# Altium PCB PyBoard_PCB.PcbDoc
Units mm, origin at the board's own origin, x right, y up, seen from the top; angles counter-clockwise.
Board outline 70.69 x 58.01 mm, 2 copper layers (Top Layer, Bottom Layer); 72 components, 78 nets, 255 pads, 64 vias.
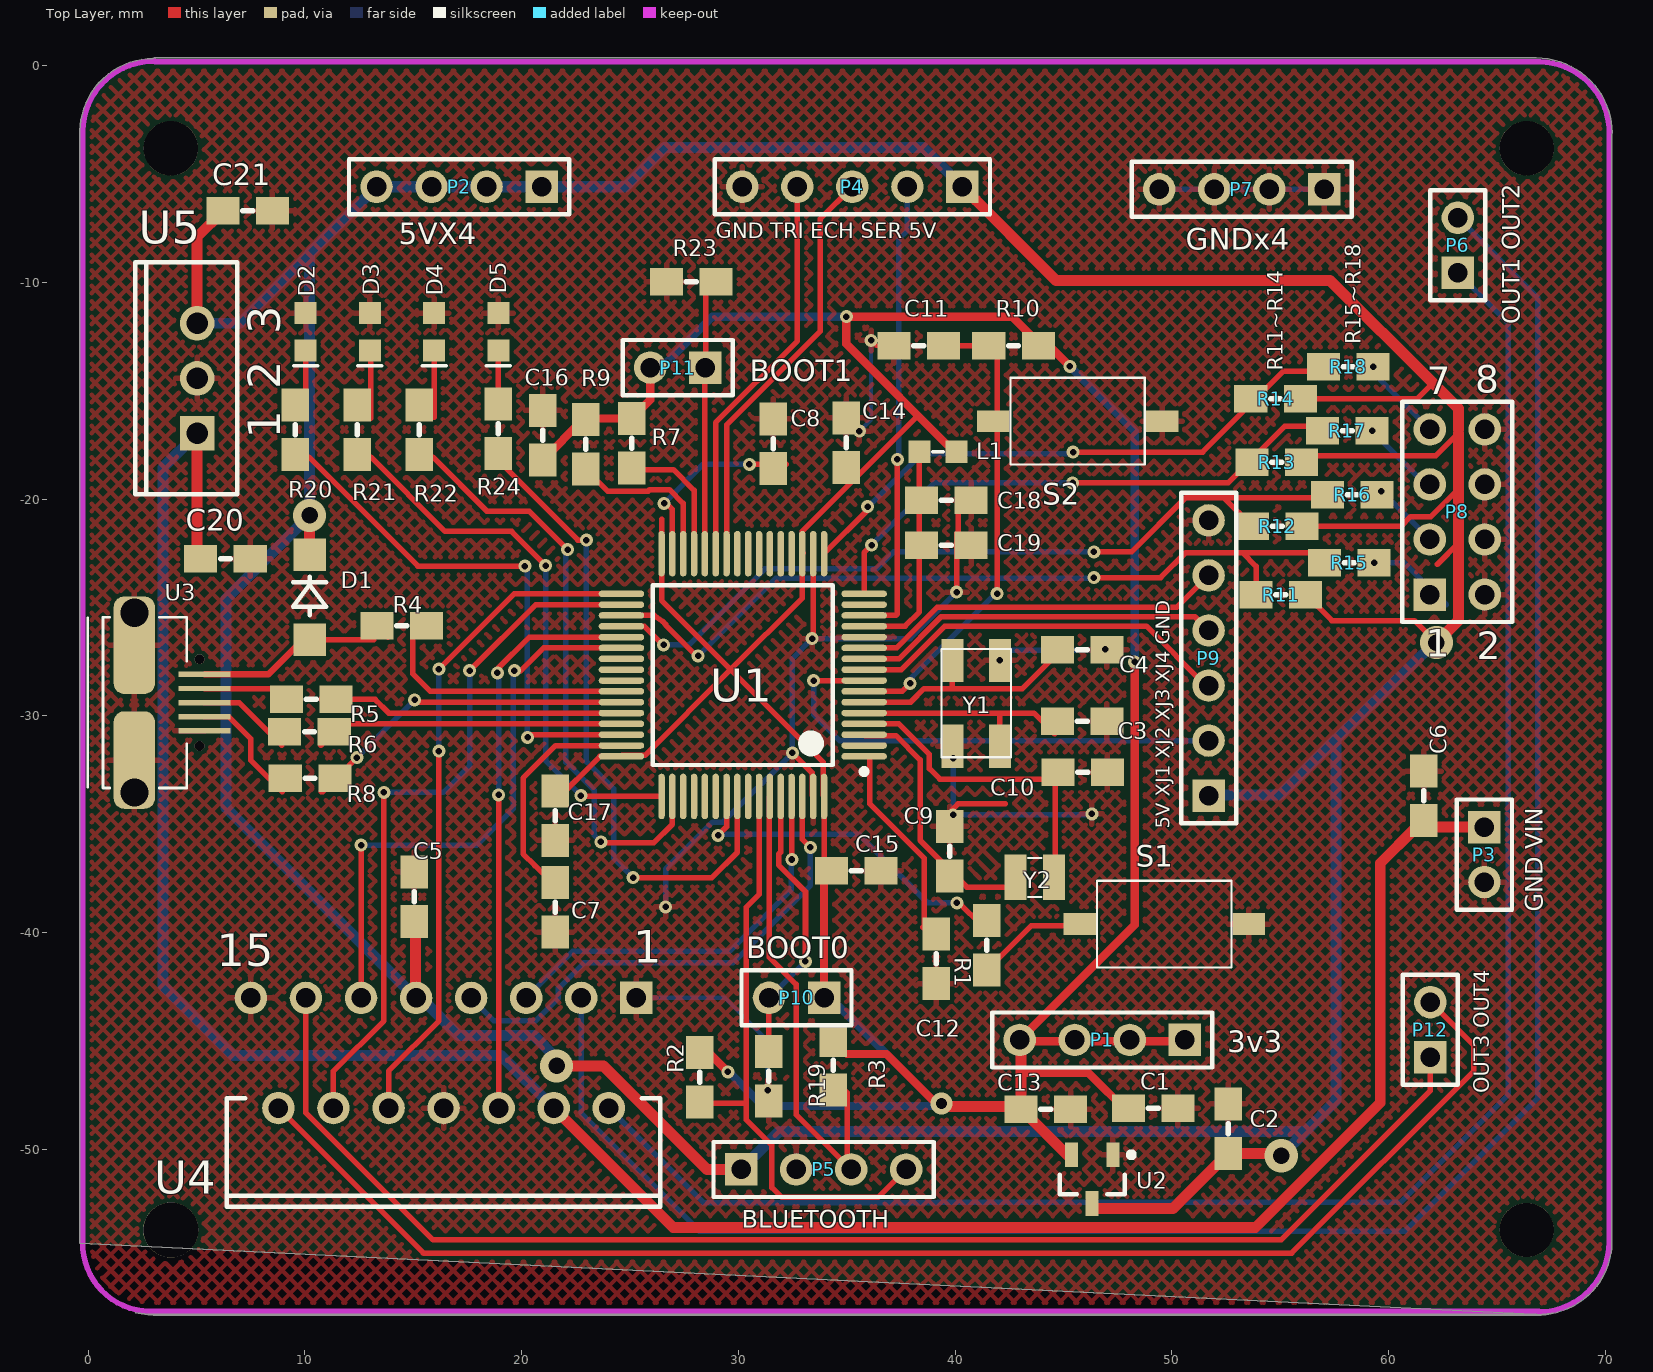
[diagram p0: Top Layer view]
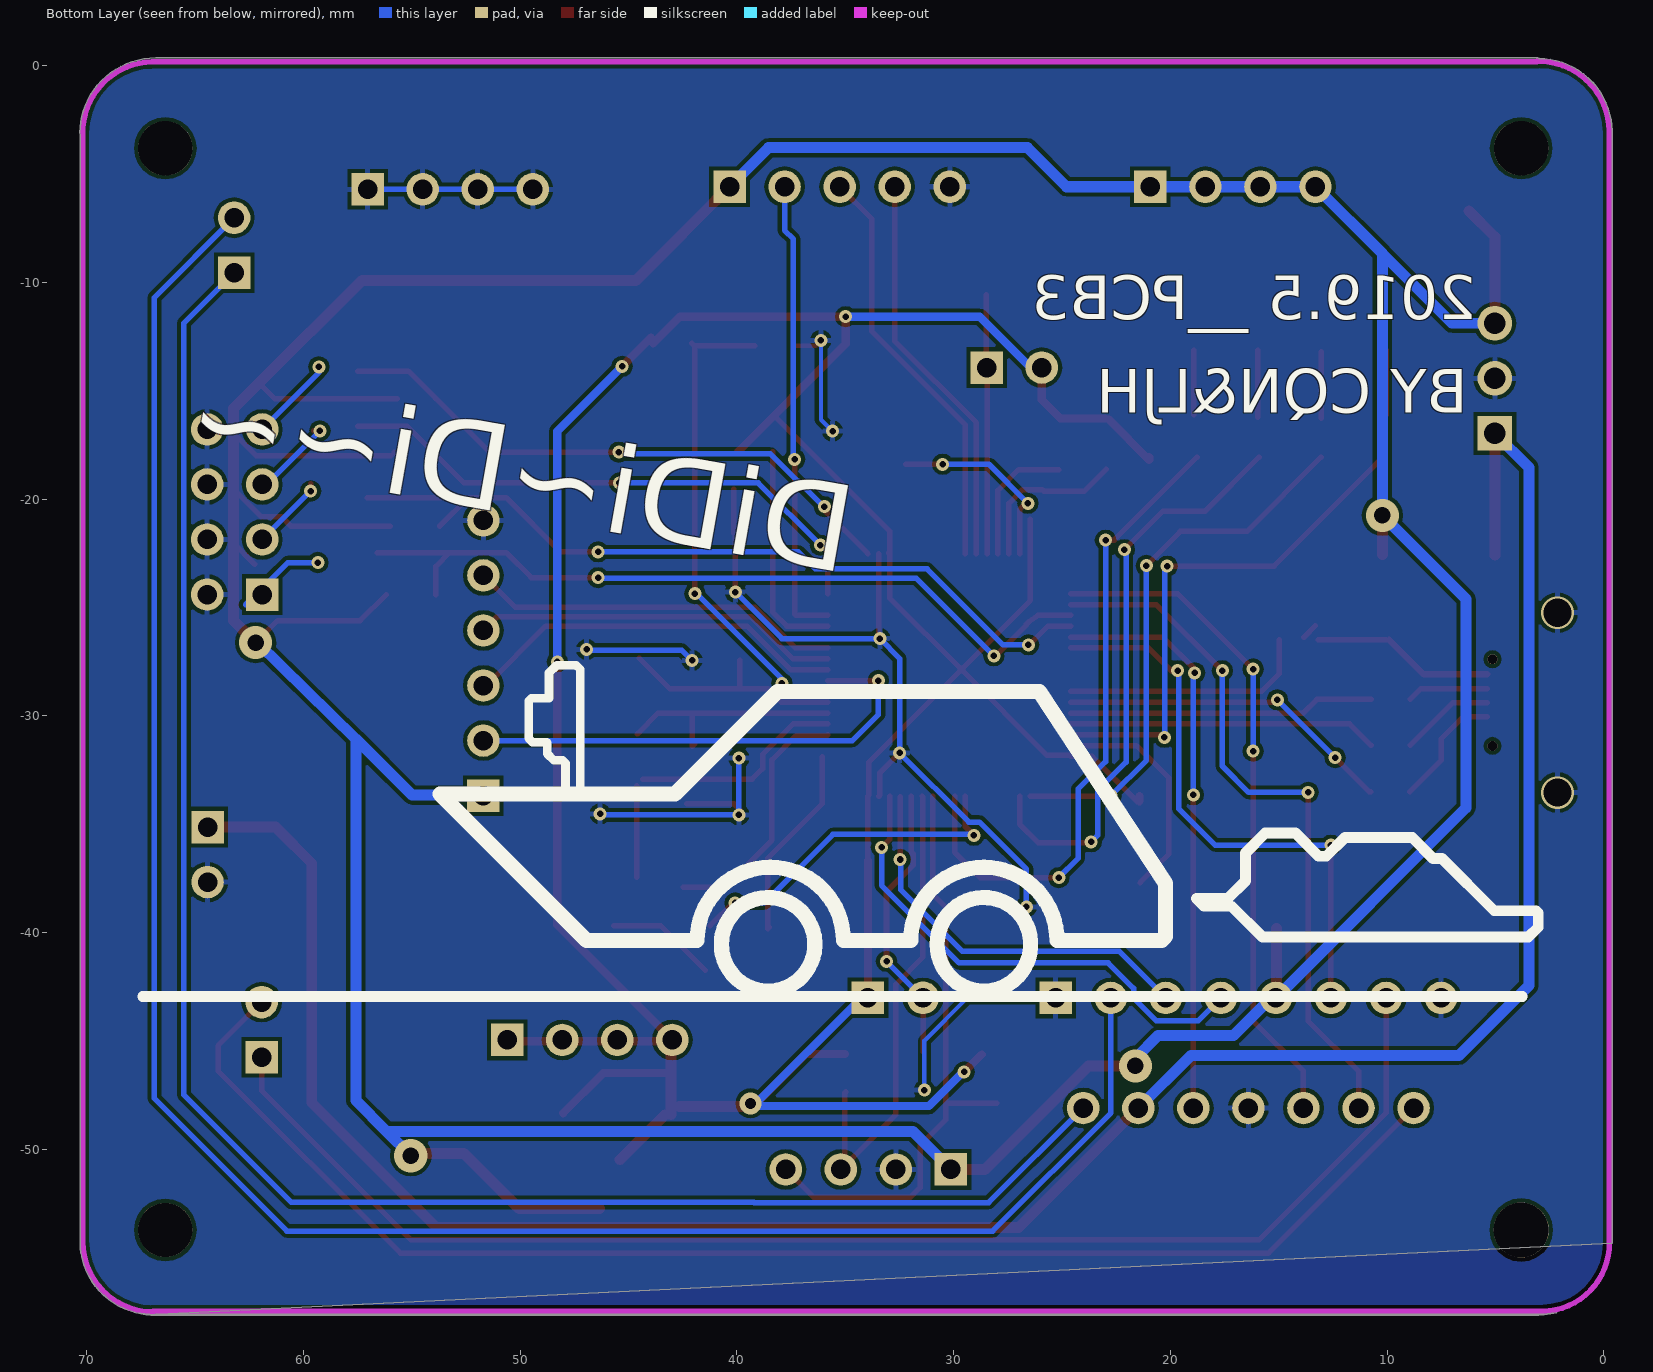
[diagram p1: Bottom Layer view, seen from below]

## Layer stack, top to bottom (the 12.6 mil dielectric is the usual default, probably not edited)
Top Layer: signal copper 0.0356
Dielectric: dielectric 0.32, FR-4, Dk 4.8
Bottom Layer: signal copper 0.0356

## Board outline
-0.381,-54.323 cw(c-0.254,-54.319) -0.381,-54.319 -0.381,-2.997 cw(c-0.254,-2.997) -0.381,-2.995 cw(c3.01,-3.061) -0.286,-2.259 cw(c3.01,-3.061) 2.208,0.235 cw(c3.01,-3.061) 2.972,0.331 cw(c3.048,0.229) 3.03,0.355 cw(c3.048,0.229) 3.048,0.356 66.802,0.356 cw(c66.802,-3.175) 68.892,-0.329 cw(c66.916,-3.086) 70.075,-1.849 cw(c66.916,-3.086) 70.308,-3.086 cw(c66.916,-3.086) 70.308,-3.099 cw(c66.916,-3.086) 70.308,-3.151 cw(c66.916,-3.086) 70.308,-3.152 70.308,-3.151 70.308,-54.305 cw(c70.18,-54.305) 70.308,-54.308 cw(c66.916,-54.242) 70.212,-55.044 cw(c66.916,-54.242) 67.718,-57.537 cw(c66.916,-54.242) 66.878,-57.633 cw(c66.916,-54.242) 66.85,-57.633 cw(c66.853,-57.506) 66.773,-57.605 2.819,-57.605 cw(c2.819,-57.478) 2.817,-57.605 cw(c2.88,-54.344) 2.179,-57.53 ccw(c3.124,-54.127) 3.03,-57.657 ccw(c3.124,-54.127) 3.124,-57.658 ccw(c3.124,-57.531) 3.228,-57.605 3.048,-57.658 cw(c3.048,-57.531) 3.03,-57.657 cw(c3.048,-57.531) 2.944,-57.605 3.048,-57.658 66.802,-57.658 ccw(c66.802,-54.127) 67.718,-57.537 66.878,-57.633 cw(c66.802,-57.531) 66.802,-57.658 cw(c66.802,-57.531)

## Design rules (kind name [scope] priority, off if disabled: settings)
Clearance [All] p1: gap=0.178
PolygonConnect [All] p1: connectstyle=Relief reliefconductorwidth=0.254 reliefentries=4 polygonreliefangle="90 Angle"
RoutingVias [All] p1: holewidth=0.3 width=0.6 viastyle="Through Hole" minholewidth=0.2 minwidth=0.5 maxholewidth=1.27 maxwidth=3.81
SilkscreenOverComponentPads [All] p1: minsilkscreentomaskgap=0.254
SolderMaskExpansion [All] p1: expansion=0.102
TestPointUsage [All] p1: valid=0 allowmultiple=FALSE
Testpoint [All] p1: side=15 testpointundercomponent=TRUE minsize=1.016 maxsize=2.54 preferedsize=1.524 minholesize=0 maxholesize=1.016 preferedholesize=0.813 testpointgrid=0.025 style=1023 order=0123456789
Width [All] p1: maxlimit=0.508 minlimit=0.178 preferedwidth=0.203
23 further rules are at their usual default settings.

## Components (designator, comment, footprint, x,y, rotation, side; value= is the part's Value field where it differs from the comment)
C1 "4u7" SMD0805 50.275,-48.1 r180 top
C2 "2u2" SMD0805 52.596,-47.905 r270 top
C3 "18p" SMD0805 47,-30.25 r180 top
C4 "18p" SMD0805 47,-26.95 r180 top
C5 "100n" SMD0805 15.05,-37.2 r270 top
C6 "100n" SMD0805 61.625,-32.55 r270 top
C7 "4u7" SMD0805 21.55,-39.975 r90 top
C8 "4u7" SMD0805 31.6,-16.3 r270 top
C9 "2.2p" SMD0805 39.75,-35.1 r270 top
C10 "2.2p" SMD0805 47.025,-32.6 r180 top
C11 "104" SMD0805 37.175,-12.915 r0 top
C12 "104" SMD0805 39.125,-42.35 r90 top
C13 "2u2" SMD0805 45.325,-48.15 r180 top
C14 "104" SMD0805 34.975,-16.25 r270 top
C15 "104" SMD0805 36.575,-37.15 r180 top
C16 "104" SMD0805 20.975,-15.9 r270 top
C17 "104" SMD0805 21.55,-35.75 r90 top
C18 "4u7" SMD0805 38.445,-20.05 r0 top
C19 "104" SMD0805 38.445,-22.125 r0 top
C20 "0.33u" SMD0805 7.475,-22.75 r180 top
C21 "0.1u" SMD0805 8.5,-6.7 r180 top
D1 "Diode" "SS24 - SMALL" 10.211,-26.492 r90 top
D2 "LED RED" LED0603 10.025,-12.275 r90 top
D3 "LED GREEN" LED0603 12.992,-12.275 r90 top
D4 "LED Yellow" LED0603 15.958,-12.275 r90 top
D5 "LED Blue" LED0603 18.925,-12.275 r90 top
L1 "1uH" SMD0603 39.209,-17.813 r180 top
P1 "3v3" HDR1X4 50.596,-44.955 r180 top
P2 "5VX4" HDR1X4 20.921,-5.585 r180 top
P3 "GND VIN" HDR1X2 64.421,-35.13 r270 top
P4 "Header 5_SUPERVOICE" HDR1X5 40.336,-5.585 r180 top
P5 "BLUETOOTH" HDR1X4 30.121,-50.93 r0 top
P6 "OUT1 OUT2" HDR1X2 63.196,-9.555 r90 top
P7 "GNDx4" HDR1X4 57.035,-5.705 r180 top
P8 "Header 4X2_CARLIGHTS" HDR2X4 61.9,-24.4 r90 top
P9 "5V XJ1 XJ2 XJ3 XJ4 GND" HDR1X6 51.696,-33.68 r90 top
P10 "BOOT0" HDR1X2 33.951,-43.01 r180 top
P11 "BOOT1" HDR1X2 28.471,-13.93 r180 top
P12 "OUT3 OUT4" HDR1X2 61.925,-45.75 r90 top
R1 "10K" SMD0805 41.465,-41.729 r90 top
R2 "4K7" SMD0805 28.225,-45.525 r270 top
R3 "4K7" SMD0805 34.375,-44.975 r270 top
R4 "560" SMD0805 15.6,-25.85 r180 top
R5 "22" SMD0805 11.425,-29.235 r180 top
R6 "22" SMD0805 11.35,-30.725 r180 top
R7 "4K7" SMD0805 25.075,-16.275 r270 top
R8 "560" SMD0805 11.375,-32.875 r180 top
R9 "4K7" SMD0805 22.95,-16.325 r270 top
R10 "10K" SMD0805 41.55,-12.915 r0 top
R11 "4K7" SMD0805 56.175,-24.4 r180 top
R12 "4K7" SMD0805 56,-21.25 r180 top
R13 "4K7" SMD0805 55.975,-18.3 r180 top
R14 "4K7" SMD0805 55.925,-15.36 r180 top
R15 "50" SMD0805 57.05,-22.925 r0 top
R16 "50" SMD0805 57.175,-19.8 r0 top
R17 "50" SMD0805 56.95,-16.85 r0 top
R18 "50" SMD0805 57,-13.9 r0 top
R19 "10K" SMD0805 31.396,-45.491 r270 top
R20 "560" SMD0805 9.55,-15.65 r270 top
R21 "560" SMD0805 12.408,-15.65 r270 top
R22 "560" SMD0805 15.267,-15.65 r270 top
R23 "10K" SMD0805 28.975,-9.975 r180 top
R24 "560" SMD0805 18.925,-15.6 r270 top
S1 "USER" "SW 3X6" 49.646,-39.605 r0 top
S2 "SW-PB" "SW 3X6" 45.65,-16.4 r0 top
U1 "STM32F405RGT6" LQFP64_M 30.201,-28.118 r180 top
U2 "XC6206" SOT-23_N 46.325,-51.375 r270 top
U3 "MicroUSB" MICROUSB -0.025,-29.388 r180 top
U4 "L298N" Multiwatt15V 16.396,-45.555 r180 top
U5 "LM7805" TO-220AB 5.025,-14.425 r90 top
Y1 "8M" SMD5032 40.973,-29.421 r270 top
Y2 "32K" TXC_9H03200019 43.675,-37.45 r0 top

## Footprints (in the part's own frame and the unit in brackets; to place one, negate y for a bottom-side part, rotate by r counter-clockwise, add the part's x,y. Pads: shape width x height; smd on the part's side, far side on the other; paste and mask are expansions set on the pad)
HDR1X2 [mm]
  rect 1.5x1.5 hole 0.9: 1(0,0)
  round 1.5 hole 0.9: 2(2.54,0)
  silkscreen extent -1.27,-1.27 3.81,1.27
HDR1X4 [mm]
  rect 1.5x1.5 hole 0.9: 1(0,0)
  round 1.5 hole 0.9: 2(2.54,0) 3(5.08,0) 4(7.62,0)
  silkscreen extent -1.27,-1.27 8.89,1.27
HDR1X5 [mm]
  rect 1.5x1.5 hole 0.9: 1(0,0)
  round 1.5 hole 0.9: 2(2.54,0) 3(5.08,0) 4(7.62,0) 5(10.16,0)
  silkscreen extent -1.27,-1.27 11.43,1.27
HDR1X6 [mm]
  rect 1.5x1.5 hole 0.9: 1(0,0)
  round 1.5 hole 0.9: 2(2.54,0) 3(5.08,0) 4(7.62,0) 5(10.16,0) 6(12.7,0)
  silkscreen extent -1.27,-1.27 13.97,1.27
HDR2X4 [mm]
  rect 1.5x1.5 hole 0.9: 1(0,0)
  round 1.5 hole 0.9: 2(0,-2.54) 3(2.54,0) 4(2.54,-2.54) 5(5.08,0) 6(5.08,-2.54) 7(7.62,0) 8(7.62,-2.54)
  silkscreen extent -1.27,-3.81 8.89,1.27
LED0603 [mil]
  rect 40x40 smd: 1(-34,0) 2(34,0)
  silkscreen extent -62,-22 -62,22
LQFP64_M [mm]
  oval 2.1x0.3 smd: 1(-5.6,3.75) 2(-5.6,3.25) 3(-5.6,2.75) 4(-5.6,2.25) 5(-5.6,1.75) 6(-5.6,1.25) 7(-5.6,0.75) 8(-5.6,0.25) 9(-5.6,-0.25) 10(-5.6,-0.75) 11(-5.6,-1.25) 12(-5.6,-1.75) 13(-5.6,-2.25) 14(-5.6,-2.75) 15(-5.6,-3.25) 16(-5.6,-3.75) 33(5.6,-3.75) 34(5.6,-3.25) 35(5.6,-2.75) 36(5.6,-2.25) 37(5.6,-1.75) 38(5.6,-1.25) 39(5.6,-0.75) 40(5.6,-0.25) 41(5.6,0.25) 42(5.6,0.75) 43(5.6,1.25) 44(5.6,1.75) 45(5.6,2.25) 46(5.6,2.75) 47(5.6,3.25) 48(5.6,3.75)
  oval 0.3x2.1 smd: 17(-3.75,-5.6) 18(-3.25,-5.6) 19(-2.75,-5.6) 20(-2.25,-5.6) 21(-1.75,-5.6) 22(-1.25,-5.6) 23(-0.75,-5.6) 24(-0.25,-5.6) 25(0.25,-5.6) 26(0.75,-5.6) 27(1.25,-5.6) 28(1.75,-5.6) 29(2.25,-5.6) 30(2.75,-5.6) 31(3.25,-5.6) 32(3.75,-5.6) 49(3.75,5.6) 50(3.25,5.6) 51(2.75,5.6) 52(2.25,5.6) 53(1.75,5.6) 54(1.25,5.6) 55(0.75,5.6) 56(0.25,5.6) 57(-0.25,5.6) 58(-0.75,5.6) 59(-1.25,5.6) 60(-1.75,5.6) 61(-2.25,5.6) 62(-2.75,5.6) 63(-3.25,5.6) 64(-3.75,5.6)
  silkscreen extent -5.72,-4.15 4.15,4.57, body extent -5,-5 5,5, height 1.6
MICROUSB [mm]
  rect 2.4x0.25 smd: 1(-5.4,-1.3) 2(-5.4,-0.65) 3(-5.4,0) 4(-5.4,0.65) 5(-5.4,1.3)
  rrect50% 1.9x4.5 smd: 6(-2.15,2.65) 7(-2.15,-2.65)
  round 0.457 hole 0.457 unplated: ""(-5.159,-2) ""(-5.159,2)
  silkscreen extent -4.57,-3.94 0,3.94
Multiwatt15V [mm] "TO, Thru-Hole, Vertical, Heatsink Mounted; 15 Bent Staggered Leads; Pitch 1.27 mm"
  rect 1.5x1.5 hole 0.9: 1(-8.89,-2.54)
  round 1.5 hole 0.9: 2(-7.62,2.54) 3(-6.35,-2.54) 4(-5.08,2.54) 5(-3.81,-2.54) 6(-2.54,2.54) 7(-1.27,-2.54) 8(0,2.54) 9(1.27,-2.54) 10(2.54,2.54) 11(3.81,-2.54) 12(5.08,2.54) 13(6.35,-2.54) 14(7.62,2.54) 15(8.89,-2.54)
  silkscreen extent -10,2.09 10,7.09
SMD0603 [mil]
  rect 40x40 smd: 1(-34,0) 2(34,0)
  silkscreen extent -10,0 10,0
SMD0805 [mil]
  rect 60x50 smd: 1(0,0) 2(90,0)
  silkscreen extent 36,0 54,0
SMD5032 [mm]
  rect 2x1 smd: 1(-1.98,-1.096) 2(1.98,-1.096) 3(1.98,1.096) 4(-1.98,1.096)
  silkscreen extent -2.51,-1.6 2.49,1.6, body extent -2.41,-1.52 2.41,1.52, height 0.8
SOT-23_N [mm]
  rect 1.15x0.6 smd: 1(-1.125,0.95) 2(-1.125,-0.95) 3(1.125,0)
  silkscreen extent -1.25,-1.5 0.7,1.93, body extent -0.7,-1.5 0.7,1.5, height 1.1
"SS24 - SMALL" [mm]
  rect 1.5x1.5 smd: 1(0,0) 2(3.937,0)
  silkscreen extent 1.14,-0.76 2.92,0.76, body extent -0.64,-0.89 4.57,0.89, height 3
"SW 3X6" [mm]
  rect 1.5x1 smd: 1(-3.9,0) 2(3.9,0)
  silkscreen extent -3.1,-2 3.1,2
TO-220AB [mm]
  rect 1.6x1.6 hole 1: 1(-2.54,0)
  round 1.6 hole 1: 2(0,0) 3(2.54,0)
  silkscreen extent -5.35,-1.85 5.35,2.85
TXC_9H03200019 [mm]
  rect 1x2.1 smd: 1(-0.889,0) 2(0.889,0)
  silkscreen extent -0.3,-0.9 0.3,0.9, body extent -1.4,-0.89 1.4,0.89, height 0.8

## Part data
C1 C2 C5 C6 C7 C8 C9 C10 C11 C12 C13 C14 C15 C16 C17 C18 C19 C20 C21: library part Cap, "Capacitor"
C3 C4: library part Cap
D1: "Default Diode"
D2: library part LED-RED, "红色发光二极管"
D3: library part LED-GREEN, "绿色发光二极管"
D4: library part LED-YELLOW, "黄色发光二极管"
D5: library part LED-BLUE, "蓝色发光二极管"
L1: library part Inductor, "Inductor"
P1 P2 P5 P7: library part "Header 4", "Header, 4-Pin"
P3 P6 P10 P11 P12: library part "Header 2", "Header, 2-Pin"
P4: library part "Header 5", "Header, 5-Pin"
P8: library part "Header 4X2", "Header, 4-Pin, Dual row"
P9: library part "Header 6", "Header, 6-Pin"
R1 R2 R3 R4 R5 R6 R7 R8 R9 R10 R11 R12 R13 R14 R15 R16 R17 R18 R19 R20 R21 R22 R23 R24: library part Res, "Resistor"
S1: library part SW-PB, "Switch"
S2: "Switch"
U1: "ARM Cortex-M4 32-bit MCU+FPU, 210 DMIPS, 1024 kB Flash, 192 kB Internal RAM, 51 I/Os, 64-pin LQFP, -40 to 85 degC, Tray"
U4: "Dual Full Bridge Driver"
Y1: library part XTAL_SMD, "SMD5032 8M 4Pin有源晶振"
Y2: library part XTAL, "Crystal Oscillator"

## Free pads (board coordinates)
  round 2.5 hole 2.5: 2(66.37,-53.721) 4(3.81,-3.81) 5(66.37,-3.81)
  round 2.54 hole 2.54: 3(3.81,-53.721)

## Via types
v1: diameter 0.6, hole 0.3, Top Layer to Bottom Layer, 57 vias
v2: diameter 1.524, hole 0.762, Top Layer to Bottom Layer, 3 vias
v3: diameter 1.5, hole 1.3, Top Layer to Bottom Layer, 2 vias
v4: diameter 1.016, hole 0.508, Top Layer to Bottom Layer, 1 vias
v5: diameter 1.534, hole 0.762, Top Layer to Bottom Layer, 1 vias

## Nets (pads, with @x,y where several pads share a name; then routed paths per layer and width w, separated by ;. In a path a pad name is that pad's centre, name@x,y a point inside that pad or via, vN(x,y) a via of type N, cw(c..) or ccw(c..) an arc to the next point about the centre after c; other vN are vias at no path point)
3V3: C1.2 C13.2 C14.2 C15.2 C16.2 C17.2 L1.1 P1.1 P1.2 P1.3 P1.4 P10.1 P11.2 R2.1 R3.1 R7.1 R9.1 R10.2 U1.19 U1.32 U1.48 U1.64 U2.2 | length 169.1
  Top Layer w0.254: C17.2@21.515,-33.962 23.609,-31.868 U1.48 24.646,-31.823 25.689,-31.823 29.644,-27.868 ; 26.451,-20.931 U1.32 26.451,-24.675 29.644,-27.868 ; U1.19@32.996,-22.473 U1.19 ; U1.64@33.905,-33.673 33.905,-32.129 29.644,-27.868 ; C15.2@33.951,-36.678 U1.64 ; 38.262,-16.163 32.951,-21.475 U1.19 ; 29.644,-27.868 32.951,-24.561 U1.19
  Top Layer w0.381: C16.2@20.975,-18.059 C16.2 R9.1@22.836,-16.325 ; C17.2@21.421,-33.941 C17.2@21.421,-33.697 ; R9.1@23,-16.275 R7.1 25.931,-15.419 P11.2 ; R2.1@28.704,-45.621 v1(29.515,-46.431) ; P10.1 C15.2@33.951,-36.678 ; 35.01,-45.596 36.833,-45.596 v4@39.116,-47.879 ; v4(39.37,-47.879) v4@39.522,-48.031 ; L1.1@39.945,-17.813 34.976,-12.843 v1(34.976,-11.582) 40.361,-11.582 42.63,-11.582 R10.2@43.863,-12.815 ; P1.4@43.025,-45.005 P1.4 48.285,-39.645 v1(48.285,-27.508) ; P1.4@43.035,-45.014 48.056,-45.014 P1.1@50.537,-45.014 ; 43.06,-46.482 46.162,-46.482 C1.2@48.01,-48.33 ; R10.2@43.958,-12.538 v1(45.288,-13.868)
  Top Layer w0.5: v4@39.522,-48.031 C13.2@42.661,-48.031 ; C13.2@43.035,-48.405 P1.4@43.035,-45.014 ; C13.2@43.315,-48.405 U2.2@45.39,-50.479
  Bottom Layer w0.381: P11.2@26.45,-13.93 28.797,-11.582 v1(34.976,-11.582) ; v1(29.515,-46.431) 29.556,-46.431 31.131,-48.006 39.243,-48.006 P10.1@34.267,-43.03 ; v1(45.288,-13.868) 48.285,-16.866 v1(48.285,-27.508)
5V: C2.2 C5.2 C21.2 D1.2 P2.1 P2.2 P2.3 P2.4 P4.1 P5.1 P9.1 R11.1 R12.1 R13.1 R14.1 U2.3 U4.9 U5.3 | length 248
  Top Layer w0.254: R13.1@55.654,-17.985 R13.1@55.804,-17.835 ; R14.1@55.679,-15.36 R14.1 61.331,-15.36 62.044,-14.647 ; R13.1@55.975,-18.004 62.168,-18.004 63.221,-16.951 63.221,-16.789 ; R12.1 60.573,-21.25 61.018,-20.805 61.948,-20.805 63.195,-19.558 ; R11.1 57.378,-25.603 61.189,-25.603 v2(62.205,-26.619) ; 62.244,-23.008 63.221,-22.031
  Top Layer w0.5: U5.3 5.025,-7.889 C21.2
  Top Layer w0.508: D1.2 v2(10.211,-20.752) ; U4.9@15.096,-42.985 C5.2@15.096,-39.818 ; v2(21.615,-46.152) 23.774,-46.152 28.552,-50.93 P5.1 ; P4.1@40.959,-6.208 P4.1 44.657,-9.906 57.302,-9.906 62.044,-14.647 63.221,-15.824 63.221,-16.789 ; U2.3@46.34,-52.729 50.057,-52.729 C2.2 54.585,-50.191 54.686,-50.292 v5@54.762,-50.292 ; v2(62.205,-26.619) 63.221,-25.603 63.221,-22.031 63.221,-16.951
  Bottom Layer w0.5: U5.3 7.001,-11.885 10.211,-8.675
  Bottom Layer w0.508: v2(21.615,-46.152) 21.615,-45.796 20.574,-44.755 17.087,-44.755 15.347,-43.015 U4.9 6.35,-34.239 6.35,-24.613 v2(10.211,-20.752) 10.211,-8.675 P2.4 P2.3 P2.2 P2.1 24.551,-5.585 24.79,-5.585 26.591,-3.785 38.535,-3.785 P4.1 ; P5.1 31.876,-49.174 56.159,-49.174 ; P9.1@51.72,-33.655 54.991,-33.655 57.582,-31.064 ; v5(55.042,-50.292) 56.159,-49.174 ; v2@62.154,-26.594 57.582,-31.064 ; 56.159,-49.174 57.582,-47.752 57.582,-31.064
BOOT0: P10.2 R19.1 U1.60 | length 13
  Top Layer w0.254: R19.1 P10.2@31.396,-43.025 ; U1.60 31.951,-36.282 31.856,-36.376 31.856,-36.877 33.095,-38.116 v1(33.095,-41.326)
  Bottom Layer w0.254: P10.2 v1(33.095,-41.326)
GND: C1.1 C2.1 C3.1 C4.1 C5.1 C6.1 C7.1 C8.1 C9.1 C10.1 C11.1 C12.1 C13.1 C14.1 C15.1 C16.1 C17.1 C18.2 C19.2 C20.1 C21.1 D2.2 D3.2 D4.2 D5.2 P3.2 P4.5 P5.2 P7.1 P7.2 P7.3 P7.4 P8.2 P8.4 P8.6 P8.8 P9.6 R19.2 R23.2 S1.2 S2.2 U1.12 U1.18 U1.63 U2.1 U3.5 U3.6 U3.7 U4.1 U4.8 U4.15 U5.2 Y1.2 Y1.4 | length 73.3
  Top Layer w0.203: v1(31.345,-47.269) R19.2@31.396,-47.218 ; v1(36.119,-12.675) 36.359,-12.915 C11.1@37.371,-12.915
  Top Layer w0.254: v1(32.487,-31.711) 33.405,-32.629 33.405,-33.673 U1.63 ; v1(33.4,-26.44) 33.451,-26.44 U1.18 ; v1(39.903,-34.569) 39.867,-34.533 39.867,-34.323 40.131,-34.059 42.317,-34.059 ; v1(40.072,-24.291) C19.2@40.072,-21.565 ; C19.2@40.138,-21.565 C18.2@40.138,-19.54
  Bottom Layer w0.203: U4.1 29.375,-43.015 31.345,-44.984 v1(31.345,-47.269) ; v1(35.585,-16.866) 36.119,-16.332 v1(36.119,-12.675)
  Bottom Layer w0.254: v1(26.645,-38.811) 26.645,-37.067 28.807,-34.904 29.293,-34.904 v1(32.487,-31.711) 32.487,-30.074 32.487,-27.353 v1(33.4,-26.44) 37.923,-26.44 v1(40.072,-24.291) ; v1(39.903,-34.569) 46.253,-34.569 v1(46.304,-34.519) ; v1@39.903,-34.287 v1(39.903,-31.953) ; v1(42.069,-27.441) 42.549,-26.962 v1@46.872,-26.962 ; P7.4 P7.3 P7.2 P7.1
  other v1: 46.931,-26.937
  other v3: 2.134,-33.538 2.134,-25.238
L298N_OUT1: P6.1 U4.2 | length 84.3
  Bottom Layer w0.254: U4.2 28.38,-52.46 39.203,-52.46 39.211,-52.451 60.554,-52.451 65.515,-47.489 65.515,-11.875 P6.1
L298N_OUT2: P6.2 U4.3 | length 96.4
  Bottom Layer w0.254: U4.3 22.746,-48.317 28.201,-53.772 60.757,-53.772 66.878,-47.65 66.878,-10.697 P6.2
L298N_OUT3: P12.1 U4.13 | length 64
  Top Layer w0.254: U4.13 10.046,-48.317 15.907,-54.178 55.042,-54.178 61.925,-47.295 P12.1
L298N_OUT4: P12.2 U4.14 | length 65.4
  Top Layer w0.254: U4.14 15.469,-54.788 55.528,-54.788 63.932,-46.384 63.932,-45.217 P12.2
NetC3_2: C3.2 U1.5 Y1.3 | length 10.9
  Top Layer w0.254: U1.5 43.628,-29.868 C3.2@44.587,-30.827 ; Y1.3@41.936,-31.269 Y1.3 42.069,-29.912
NetC4_2: C4.2 U1.6 Y1.1 | length 12
  Top Layer w0.254: U1.6@36.844,-29.368 U1.6 37.95,-29.368 38.572,-28.746 43.101,-28.746 C4.2@44.512,-27.335 ; 39.877,-28.722 Y1.1 Y1.1@39.877,-27.528
NetC7_2: C7.2 U1.47 | length 10.5
  Top Layer w0.254: C7.2@21.396,-37.694 20.608,-36.906 20.066,-36.364 20.066,-32.868 21.566,-31.368 U1.47
NetC8_2: C8.2 U1.31 | length 8.9
  Top Layer w0.254: v1(26.568,-20.193) 26.67,-20.193 26.951,-20.474 U1.31 ; v1(30.505,-18.39) C8.2@32.207,-18.39
  Bottom Layer w0.254: v1(26.568,-20.193) 28.372,-18.39 v1(30.505,-18.39)
NetC9_2: C9.2 U1.3 Y2.1 | length 11.8
  Top Layer w0.254: U1.3 35.846,-30.913 37.263,-30.913 38.379,-32.029 38.379,-35.738 40.538,-37.897 41.25,-37.897 Y2.1@42.469,-37.897
NetC10_2: C10.2 U1.4 Y2.2 | length 14.2
  Top Layer w0.254: U1.4 37.404,-30.368 38.811,-31.775 38.811,-32.436 39.294,-32.918 C10.2@44.348,-32.918 ; Y2.2@44.612,-37.45 C10.2@44.612,-33.235
NetC11_2: C11.2 R10.1 S2.1 U1.7 | length 22.5
  Top Layer w0.254: U1.7 37.553,-28.868 v1(37.922,-28.499) ; C11.2@39.163,-12.915 R10.1@41.971,-12.915 ; v1(41.935,-24.359) 41.935,-12.95 R10.1@41.971,-12.915 ; R10.1@42.071,-12.815 R10.1@41.971,-12.915
  Bottom Layer w0.254: v1(37.922,-28.499) 37.922,-28.299 41.863,-24.359 v1(41.935,-24.359)
NetC18_1: C18.1 C19.1 L1.2 U1.13 | length 10.2
  Top Layer w0.254: U1.13@35.811,-25.857 37.694,-25.857 38.345,-25.206 L1.2
NetD2_1: D2.1 R20.1 | length 3
  Top Layer w0.254: R20.1@10.025,-16.111 D2.1
NetD3_1: D3.1 R21.1 | length 3.1
  Top Layer w0.254: 13.043,-16.271 D3.1@13.043,-13.19
NetD4_1: D4.1 R22.1 | length 3.1
  Top Layer w0.254: 15.958,-16.214 D4.1
NetD5_1: D5.1 R24.1 | length 3
  Top Layer w0.254: R24.1@18.925,-16.106 D5.1
NetP8_1: P8.1 R15.2 | length 4.4
  Bottom Layer w0.254: v1(59.336,-22.925) 60.72,-22.925 62.662,-24.867 ; P8.1 P8.1@61.9,-24.105
NetP8_3: P8.3 R16.2 | length 3.5
  Top Layer w0.254: v1(59.665,-19.625) R16.2@59.665,-19.292
  Bottom Layer w0.254: v1(59.665,-19.625) P8.3
NetP8_5: P8.5 R17.2 | length 3.8
  Top Layer w0.254: v1(59.236,-16.85) R17.2@59.522,-16.85
  Bottom Layer w0.254: v1(59.236,-16.85) P8.5@61.706,-19.32
NetP8_7: P8.7 R18.2 | length 3.7
  Bottom Layer w0.254: v1@59.286,-14.166 P8.7
  other v1: 59.286,-13.9
NetR1_1: R1.1 S1.1 | length 5.1
  Top Layer w0.254: R1.1 43.514,-39.68 S1.1@45.671,-39.68
NetR5_2: R5.2 U3.2 | length 3.8
  Top Layer w0.254: U3.2 8.44,-28.738 R5.2@8.937,-29.235
NetR6_2: R6.2 U3.3 | length 4.4
  Top Layer w0.254: U3.3 6.965,-29.388 R6.2@8.937,-31.36
NetR8_2: R8.2 U3.4 | length 5.6
  Top Layer w0.254: U3.4 6.481,-30.038 7.493,-31.05 7.493,-32.041 R8.2@8.962,-33.51
PA0_X1_SERVO: P4.2 U1.14 | length 21.6
  Top Layer w0.254: U1.14 37.269,-25.368 37.338,-25.298 v1(37.338,-18.161)
  Bottom Layer w0.254: v1(37.338,-18.161) 37.389,-18.161 37.389,-8.001 37.796,-7.594 P4.2 ; P4.2@37.492,-5.815 P4.2@37.567,-5.815
PA1_X2: U1.15
PA2_X3_LEFTL: R13.2 R17.1 U1.16 | length 26
  Top Layer w0.254: U1.16 35.801,-22.467 v1(36.144,-22.123) ; v1(45.415,-19.253) 52.594,-19.253 53.862,-17.985 55.207,-16.64 R17.1@57.496,-16.64
  Bottom Layer w0.254: v1(36.144,-22.123) 39.014,-19.253 v1(45.415,-19.253)
PA3_X3_RIGHTL: R14.2 R18.1 U1.17 | length 26.9
  Top Layer w0.254: U1.17 v1@35.966,-20.502 ; v1(45.441,-17.831) 51.416,-17.831 53.887,-15.36 55.157,-14.09 R18.1@57.496,-14.09
  Bottom Layer w0.254: v1(35.966,-20.345) 36.009,-20.345 38.447,-17.907 v1@45.39,-17.907
PA4_X5: U1.20
PA5_X6: U1.21
PA6_X7: U1.22
PA7_X8: U1.23
PA8_SDIO_SW: U1.41
PA9_VSUB: R4.1 U1.42 | length 11.5
  Top Layer w0.254: R4.1@14.979,-26.485 14.979,-28.06 15.773,-28.854 U1.42@24.587,-28.854
PA10_ID: R8.1 U1.43 | length 15.7
  Top Layer w0.254: R8.1@10.754,-33.51 10.813,-33.51 v1(12.395,-31.928) ; v1(15.062,-29.261) 15.169,-29.368 U1.43
  Bottom Layer w0.254: v1(12.395,-31.928) v1(15.062,-29.261)
PA11_DM: R5.1 U1.44 | length 14.1
  Top Layer w0.254: R5.1@10.729,-29.235 13.232,-29.235 13.865,-29.868 U1.44
PA12_DP: R6.1 U1.45 | length 14.3
  Top Layer w0.254: R6.1@10.729,-31.36 11.721,-30.368 U1.45
PA13_P5_RED: R20.2 U1.46 | length 24.4
  Top Layer w0.254: 10.185,-18.063 15.211,-23.089 v1(20.142,-23.089) ; v1(20.269,-30.988) 20.389,-30.868 U1.46
  Bottom Layer w0.254: v1(20.142,-23.089) 20.264,-23.211 v1@20.264,-30.983
PA14_P4_GRN: R21.2 U1.49 | length 25.2
  Top Layer w0.254: 13.043,-18.063 16.469,-21.488 19.533,-21.488 v1(21.107,-23.063) ; v1(22.733,-33.68) 22.77,-33.718 U1.49
  Bottom Layer w0.254: v1(21.107,-23.063) 21.107,-32.055 v1(22.733,-33.68)
PA15_P3_YEL: R22.2 U1.50 | length 27
  Top Layer w0.254: 15.902,-18.063 18.387,-20.549 20.345,-20.549 v1(22.123,-22.327) ; v1(23.647,-35.814) 23.698,-35.865 26.086,-35.865 26.951,-35 U1.50
  Bottom Layer w0.254: v1@22.039,-22.411 22.039,-32.131 23.338,-33.43 23.338,-35.504 v1(23.647,-35.814)
PB0_Y11_ECHO: P4.3 U1.26 | length 19.3
  Top Layer w0.254: U1.26 29.451,-16.574 33.771,-12.254 33.771,-7.07 P4.3
PB1_Y12_TRIG: P4.4 U1.27 | length 18.5
  Top Layer w0.254: U1.27 28.951,-16.464 32.716,-12.698 P4.4
PB2_BOOT1: P11.1 R23.1 U1.28 | length 11.9
  Top Layer w0.254: U1.28 P11.1@28.451,-13.95 ; P11.1@28.484,-13.916 R23.1@28.484,-10.566
PB3_X17_SW: R1.2 U1.55 | length 15.8
  Top Layer w0.254: v1(29.058,-35.509) 29.451,-35.116 U1.55 ; v1(40.081,-38.633) 40.186,-38.633 R1.2@41.232,-39.68
  Bottom Layer w0.254: v1@29.104,-35.463 35.565,-35.463 38.735,-38.633 v1(40.081,-38.633)
PB4_P2_BLUE: R24.2 U1.56 | length 30.3
  Top Layer w0.254: R24.2@18.76,-18.063 22.592,-21.895 v1(22.987,-21.895) ; v1(25.146,-37.465) 28.778,-37.465 29.951,-36.293 U1.56
  Bottom Layer w0.254: v1@23.165,-21.895 v1(22.987,-21.895) 22.987,-32.106 24.252,-33.371 24.252,-36.571 v1(25.146,-37.465)
PB5: U1.57
PB6_X9_TX: P5.4 R2.2 U1.58 | length 28
  Top Layer w0.254: R2.2@28.016,-47.868 30.345,-47.868 ; U1.58 30.951,-38.239 30.356,-38.834 30.356,-46.137 30.356,-48.625 31.547,-49.816 31.547,-51.765 32.004,-52.222 34.442,-52.222 36.448,-52.222 P5.4
PB7_X10_RX: P5.3 R3.2 U1.59 | length 22.2
  Top Layer w0.254: U1.59 31.425,-33.744 31.425,-41.147 32.664,-42.387 32.664,-48.394 P5.3@35.01,-50.739 ; R3.2@34.968,-47.346 35.01,-47.388 P5.3@35.01,-50.739 ; P5.3 P5.3@35.01,-50.739
PB8_Y3: U1.61 U4.5 | length 18.5
  Top Layer w0.254: v1(32.461,-36.627) U1.61@32.461,-33.728
  Bottom Layer w0.254: U4.5 22.352,-40.869 29.591,-40.869 32.436,-38.024 v1@32.436,-36.678
PB9_Y4: U1.62 U4.7 | length 23.2
  Top Layer w0.254: U1.62 32.951,-35.694 v1(33.325,-36.068)
  Bottom Layer w0.254: U4.7 18.72,-44.07 20.643,-44.07 21.691,-43.021 21.691,-42.578 22.867,-41.402 29.743,-41.402 33.325,-37.821 v1(33.325,-36.068)
PB10_Y9_SCL: R7.2 U1.29 | length 6.1
  Top Layer w0.254: R7.2@25.152,-18.638 26.995,-18.638 27.951,-19.594 U1.29
PB11_Y10_SDA: R9.2 U1.30 | length 7.5
  Top Layer w0.254: R9.2 23.967,-19.628 25.836,-19.628 25.9,-19.564 26.819,-19.564 27.451,-20.195 U1.30
PB12_Y5: U1.33 U4.10 | length 31.1
  Top Layer w0.254: U4.10 13.856,-46.394 16.18,-44.07 v1(16.18,-31.624) ; v1(16.18,-27.839) 19.652,-24.368 U1.33
  Bottom Layer w0.254: v1(16.18,-31.624) v1(16.18,-27.839)
PB13_Y6: U1.34 U4.12 | length 32.6
  Top Layer w0.254: U4.12 11.316,-46.394 13.64,-44.07 v1(13.64,-33.529) ; v1(17.602,-27.915) 20.649,-24.868 U1.34
  Bottom Layer w0.254: v1(13.64,-33.529) 16.382,-33.529 17.602,-32.309 v1@17.602,-27.94
PB14_Y7_HEADL: R11.2 R15.1 U1.35 | length 36.7
  Top Layer w0.254: U1.35 26.104,-25.368 26.492,-25.629 26.645,-25.781 ; 26.645,-25.806 v1@28.067,-27.229 ; v1(46.406,-23.622) 49.484,-23.622 50.641,-22.465 53.25,-22.465 ; R11.2 53.889,-23.104 53.25,-22.465 ; R15.1@56.59,-22.465 53.25,-22.465
  Bottom Layer w0.254: v1(28.143,-27.229) 31.725,-23.647 v1@46.279,-23.647
PB15_Y8_STOPL: R12.2 R16.1 U1.36 | length 37.5
  Top Layer w0.254: U1.36 25.665,-25.868 v1@26.518,-26.721 ; v1(46.406,-22.428) 48.138,-22.428 50.641,-19.925 52.389,-19.925 ; R12.2 52.389,-19.925 ; R16.1@57.05,-19.925 52.389,-19.925
  Bottom Layer w0.254: v1(26.543,-26.721) 27.711,-26.721 31.217,-23.216 36.373,-23.216 37.16,-22.428 v1(46.406,-22.428)
PC0_X19_XJ1: P9.2 U1.8 | length 22.6
  Top Layer w0.254: v1(33.473,-28.368) U1.8
  Bottom Layer w0.254: v1(33.473,-28.368) 33.473,-29.943 34.67,-31.14 P9.2
PC1_X20_XJ2: P9.3 U1.9 | length 17.9
  Top Layer w0.254: U1.9 37.519,-27.868 39.53,-25.857 48.819,-25.857 51.561,-28.6 P9.3
PC2_X21_XJ3: P9.4 U1.10 | length 17
  Top Layer w0.254: U1.10 37.409,-27.368 39.351,-25.425 51.061,-25.425 P9.4
PC3_X22_XJ4: P9.5 U1.11 | length 17.3
  Top Layer w0.254: U1.11 37.298,-26.868 39.172,-24.994 50.222,-24.994 P9.5
PC4_X11: U1.24
PC5_X12: U1.25
PC6_Y1: U1.37 U4.6 | length 26.6
  Top Layer w0.254: v1(18.872,-28.016) 18.872,-27.847 20.351,-26.368 U1.37 ; U4.6 v1(18.936,-33.642)
  Bottom Layer w0.254: v1(18.936,-33.642) v1@18.936,-28.054
PC7_Y2: U1.38 U4.11 | length 26.3
  Top Layer w0.254: U4.11 v1(12.586,-35.966) ; v1(19.66,-27.915) 19.959,-27.915 21.006,-26.868 22.586,-26.868 U1.38
  Bottom Layer w0.254: v1(12.586,-35.966) 17.932,-35.966 19.609,-34.29 v1@19.609,-28.118
PC8_SDIO_D0: U1.39
PC9_SDIO_D1: U1.40
PC10_SDIO_D2: U1.51
PC11_SDIO_D3: U1.52
PC12_SDIO_CK: U1.53
PC13_X18: U1.2
PD2: U1.54
VBAT: C12.2 U1.1 | length 9.1
  Top Layer w0.254: U1.1@36.068,-31.877 36.068,-34.061 38.571,-36.564 38.571,-39.816 C12.2@38.499,-39.745
VBUS: D1.1 R4.2 U3.1 | length 9.1
  Top Layer w0.254: D1.1@10.057,-26.492 D1.1 13.18,-26.492 ; R4.2 R4.2@13.843,-26.379
  Top Layer w0.3: U3.1 8.311,-28.088 D1.1@9.906,-26.492
VIN: C6.2 C20.2 P3.1 U4.4 U5.1 | length 111.4
  Top Layer w0.5: C20.2@5.025,-22.586 U5.1 ; U4.4 26.99,-53.609 53.848,-53.609 ; 53.848,-53.619 59.614,-47.854 59.614,-36.826 ; 59.614,-36.8 C6.2@61.221,-35.193 ; C6.2@61.284,-35.13 P3.1
  Bottom Layer w0.5: U5.1 3.454,-18.536 3.454,-42.443 6.68,-45.669 19.05,-45.669 U4.4
pads on no net: U3.
copper on no net: | length 13.1
  Bottom Layer w0.254: 2495.194,2427.275 2508.326,2427.275

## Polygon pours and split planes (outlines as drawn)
GND on Top Layer "Bottom Layer-No Net" (hatched 45Degree grid 0.508 track 0.203, pour order 1000): -0.192,-19.532 -0.192,-54.861 ccw(c2.348,-54.861) 2.348,-57.401 5.624,-57.401 67.702,-57.401 ccw(c67.702,-54.861) 70.242,-54.861 70.242,-50.495 70.242,-2.286 ccw(c67.702,-2.286) 67.702,0.254 63.79,0.254 2.348,0.254 ccw(c2.348,-2.286) -0.192,-2.286 -0.192,-19.736
GND on Bottom Layer "Bottom Layer-No Net" (solid, pour order 1000): -0.223,-19.599 -0.223,-54.928 ccw(c2.317,-54.928) 2.317,-57.468 5.594,-57.468 67.671,-57.468 ccw(c67.671,-54.928) 70.211,-54.928 70.211,-50.562 70.211,-2.353 ccw(c67.671,-2.353) 67.671,0.187 63.76,0.187 2.317,0.187 ccw(c2.317,-2.353) -0.223,-2.353 -0.223,-19.802

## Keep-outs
Keep-Out Layer:
  lines w0.254: -0.254,-54.319 -0.254,-2.997 cw(c3.01,-3.061) 3.073,0.203 ; -0.253,-54.283 ccw(c2.88,-54.344) 2.819,-57.478 66.927,-57.478 ; 3.099,0.178 66.98,0.178 cw(c66.916,-3.086) 70.18,-3.15 ; 66.853,-57.506 ccw(c66.916,-54.242) 70.18,-54.305 70.18,-3.099

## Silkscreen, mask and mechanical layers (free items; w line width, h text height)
Top Overlay:
  text "GND TRI ECH SER 5V" at 28.956,-7.95 h0.7
  text "R15~R18" at 58.725,-12.852 h0.7 r90
  text "R11~R14" at 55.118,-14.072 h0.7 r90
Bottom Overlay:
  circle w0.7: c38.556,-40.538 r2.158
  circle w0.7: c28.599,-40.538 r2.158
  lines w0.4: 47.219,-33.604 47.219,-27.864 47.422,-27.661 48.311,-27.661 48.666,-28.016 48.666,-29.185 49.479,-29.185 49.606,-29.312 49.606,-31.039 49.428,-31.217 48.768,-31.217 48.743,-31.242 48.743,-31.75 48.438,-32.055 48.031,-32.055 47.904,-32.182 47.904,-33.604
  lines w0.5: 3.759,-42.951 67.412,-42.951 ; 3.023,-39.751 3.023,-39.091 3.124,-38.989 3.581,-38.989 5.055,-38.989 7.468,-36.576 7.874,-36.576 8.839,-35.611 11.938,-35.611 12.802,-36.474 13.157,-36.474 14.224,-35.408 15.621,-35.408 16.535,-36.322 16.535,-37.617 17.348,-38.43 18.796,-38.43 18.44,-38.786 17.17,-38.786 15.748,-40.208 14.148,-40.208 3.48,-40.208 3.023,-39.751
  lines w0.7: 20.218,-40.183 20.396,-40.361 25.228,-40.361 cw(c28.603,-40.361) 31.979,-40.361 35.083,-40.361 cw(c38.459,-40.361) 41.834,-40.361 46.939,-40.361 53.696,-33.604 47.473,-33.604 42.85,-33.604 38.125,-28.88 26.035,-28.88 20.218,-37.719 20.218,-40.183
  text "2019.5 __PCB3" at 5.893,-11.709 h2
  text "BY CQN&LJH" at 6.274,-16.002 h2
  text "DiDi~Di~~" at 35.027,-23.419 h4 r10
Mechanical 1:
  lines w0.254: 3.048,-57.531 66.802,-57.531 ccw(c66.802,-54.127) 70.206,-54.127 ; 3.048,0.229 66.802,0.229 cw(c66.802,-3.175) 70.206,-3.175 70.206,-54.153 ; 3.124,-57.531 cw(c3.124,-54.127) -0.279,-54.127 -0.279,-3.175 cw(c3.124,-3.175) 3.124,0.229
